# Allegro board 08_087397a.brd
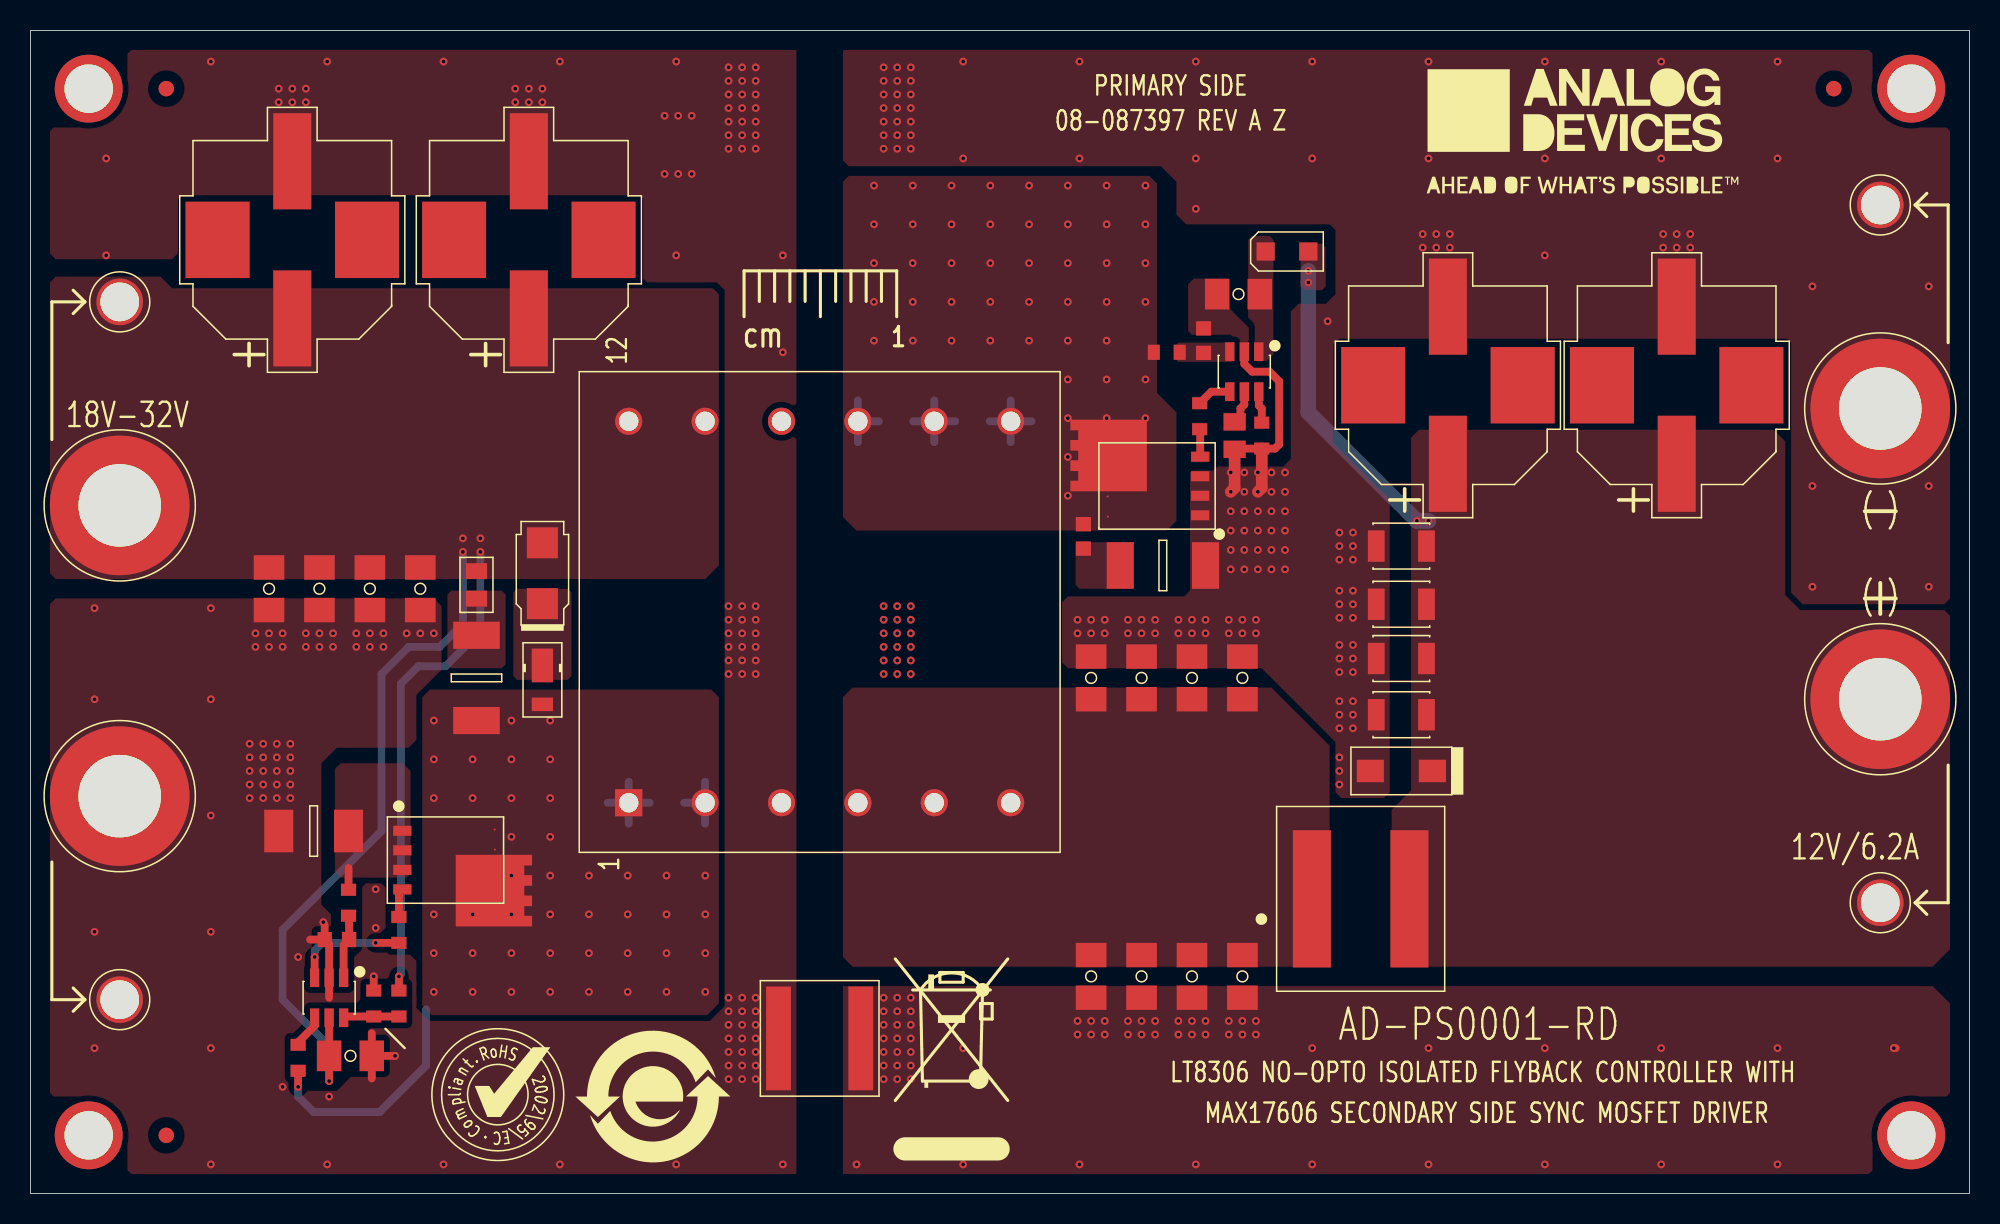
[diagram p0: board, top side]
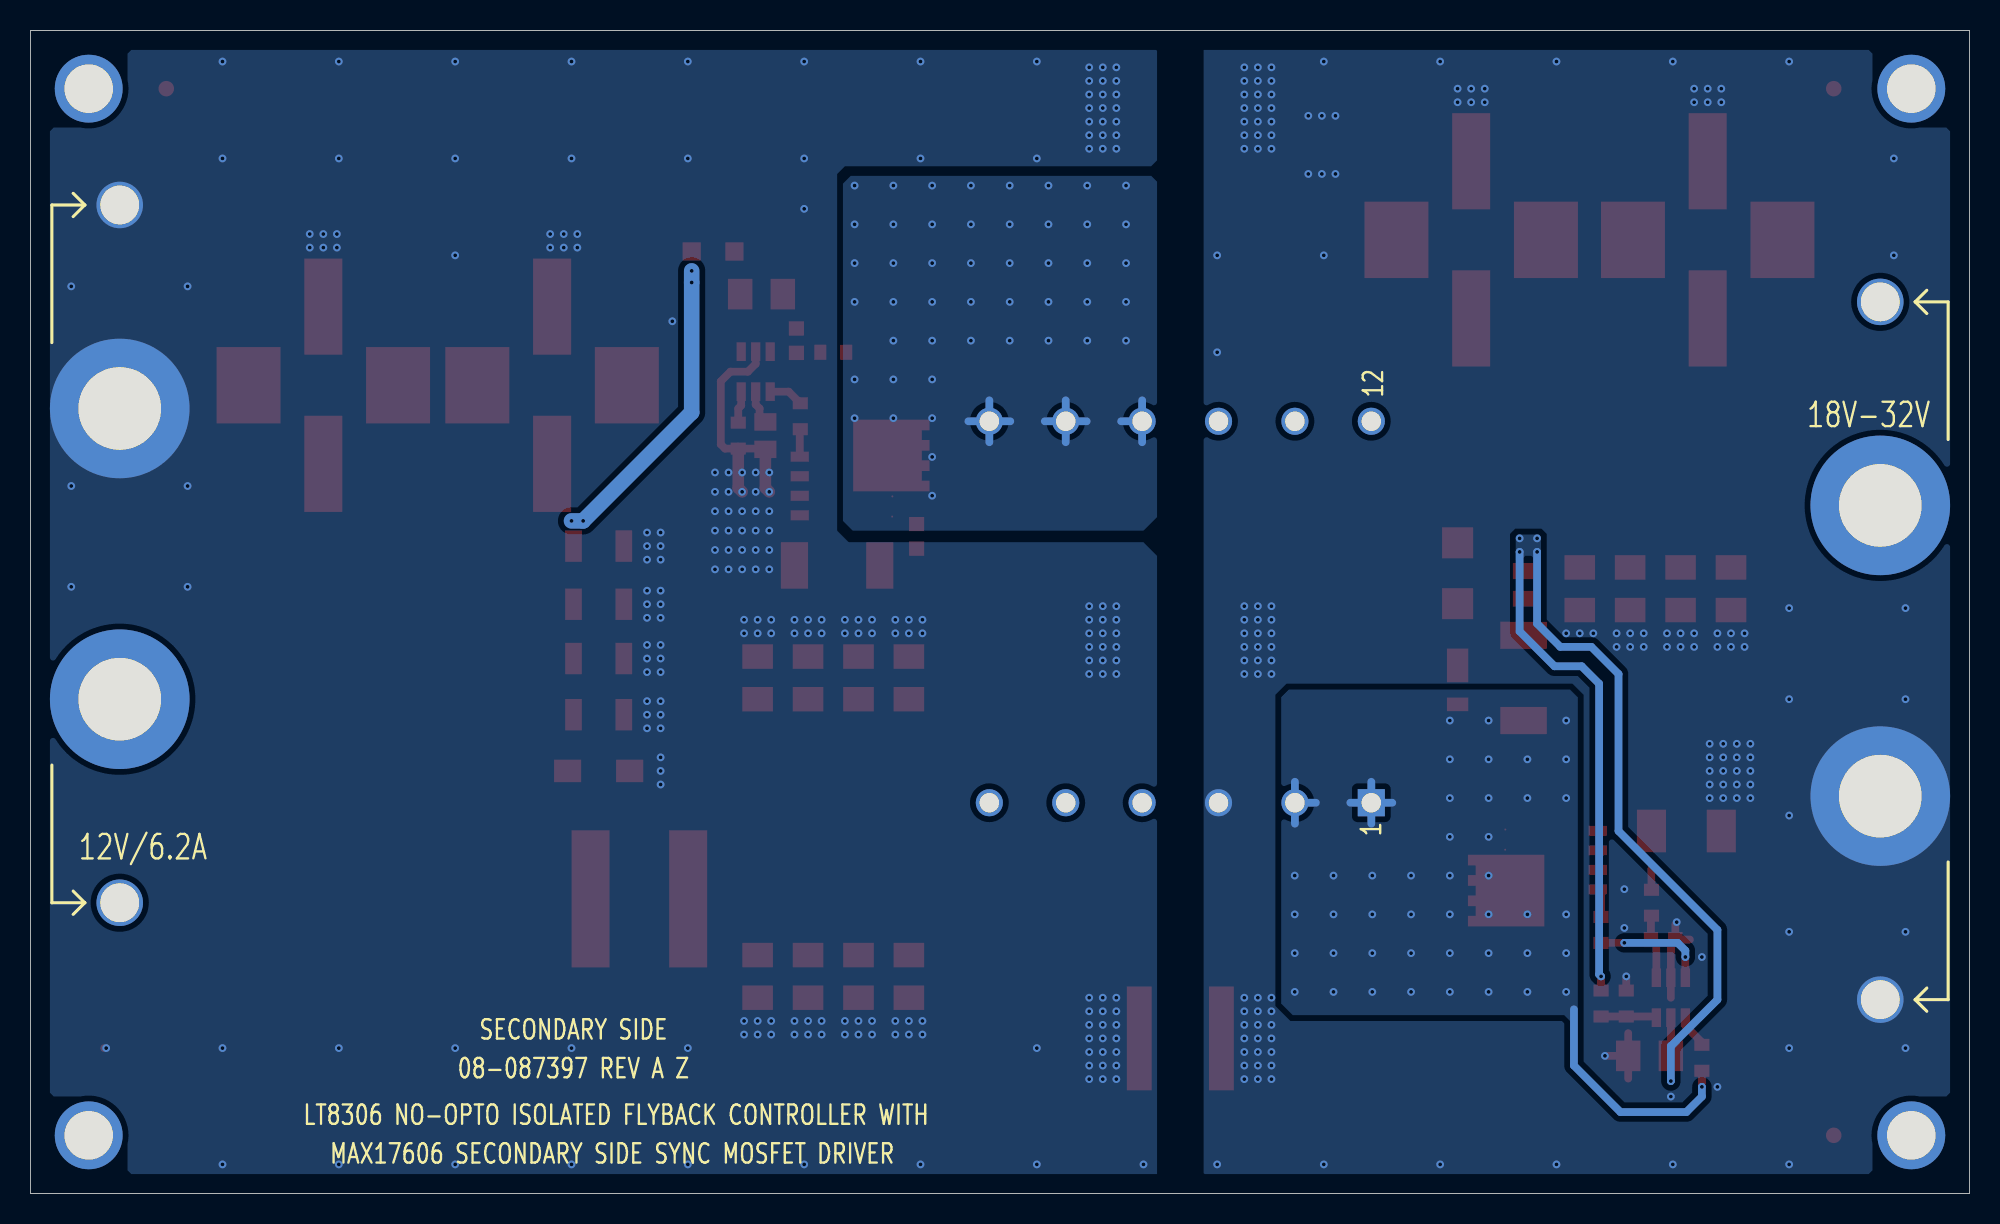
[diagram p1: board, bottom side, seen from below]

Outline 127 x 76.2 mm; copper layers: TOP, L2_GND, L3_GND, BOTTOM. Coordinates in mm from the lower left corner of the outline.
Outline path: 0,76.2 0,0 127,0 127,76.2 0,76.2

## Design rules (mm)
constraint set DEFAULT: min track width 0.203
net group UNNAMED_4_CAP_I100_N1: nets UNNAMED_4_CAP_I109_N1 UNNAMED_4_CAP_I109_N2
net group UNNAMED_4_RES_I50_N1: nets UNNAMED_4_ADMAX17606_I110_GATE UNNAMED_4_RES_I50_N1
net group VOUT: nets UNNAMED_4_CAP_I83_N2 VOUT
net group VIN: nets UNNAMED_4_ADLT8306_I22_EN UNNAMED_4_ADLT8306_I22_RFB UNNAMED_4_CAP_I31_N2 UNNAMED_4_DIOSCHOTTKY_I24_P VIN

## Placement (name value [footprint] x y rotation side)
C1  220UF  [CPLSMSQ492H650]  17.14 62.48 90 top
C2  220UF  [CPLSMSQ492H650]  32.64 62.48 90 top
C3  10uF  [C1206H71]  15.62 39.62 90 top
C4  10uF  [C1206H71]  18.92 39.62 90 top
C5  10uF  [C1206H71]  22.22 39.62 90 top
C6  10uF  [C1206H71]  25.53 39.62 90 top
C7  1uF  [C1206H71]  20.95 9.02 180 top
C8  1000pF  [C0603]  20.07 16.64 180 top
C9  680PF  [C0805H30]  29.21 39.88 270 top
C10  2200PF  [C2225H106]  51.69 10.16 0 top
C11  10uF  [C1206H71]  69.47 14.22 90 top
C12  10uF  [C1206H71]  72.77 14.22 90 top
C13  22uF  [C1210H106]  89.79 35.05 0 top
C14  10uF  [C1206H71]  76.07 14.22 90 top
C15  22uF  [C1210H106]  89.79 31.37 0 top
C16  10uF  [C1206H71]  79.38 14.22 90 top
C17  22uF  [C1210H106]  89.79 38.61 0 top
C18  22uF  [C1210H106]  89.79 42.42 0 top
C19  10uF  [C1206H71]  69.47 33.78 270 top
C20  1uF  [C1206H71]  79.12 58.93 0 top
C21  10uF  [C1206H71]  72.77 33.78 270 top
C22  220UF  [CPLSMSQ492H650]  92.84 52.96 90 top
C23  10uF  [C1206H71]  76.07 33.78 270 top
C24  220UF  [CPLSMSQ492H650]  107.82 52.96 90 top
C25  10uF  [C1206H71]  79.38 33.78 270 top
C27  1000pF  [C0603]  76.84 55.88 90 top
C30  1000pF  [C0603]  68.96 43.05 270 top
C56  2.2UF  [C0805H55]  78.87 49.66 90 top
D1  1SMA5943BT3G  [SMA]  33.53 40.64 90 top
D2  DFLS1150-7  [POWERDI123]  33.53 33.66 270 top
D3  CMZ5928B TR13 PBFREE  [DO214AC-2]  89.79 27.69 180 top
D4  CRS01(TE85L,Q,M)  [DIO-CRS]  82.3 61.72 0 top
GND  575-4  [CNBANANAD312LD203]  5.84 26.04 0 top
L1  4.7UH  [LSML413W457H358]  87.12 19.3 0 top
NOREF  -  [unnamed]  123.19 3.81 0 top
NOREF#2  -  [#2]  -109.98 -101.6 0 top
NOREF#3  -  [#2]  3.81 74.93 0 top
NOREF#4  -  [#2]  69.6 19.05 0 top
NOREF#5  -  [#2]  0 0 0 top
NOREF#6  -  [unnamed]  3.81 72.39 0 top
NOREF#7  -  [#2]  1.91 26.04 0 top
NOREF#8  -  [#2]  125.09 51.44 0 top
NOREF#9  -  [unnamed]  118.11 72.39 180 top
NOREF#10  -  [#2]  -28.75 329.56 0 top
NOREF#11  -  [#2]  -32.51 375.29 0 top
NOREF#12  -  [#2]  -9.27 209.93 0 top
NOREF#13  -  [#2]  0 76.2 270 top
NOREF#14  -  [#2]  306.6 -22.44 0 top
NOREF#15  -  [#2]  275.68 85.49 0 top
NOREF#16  -  [#2]  101.09 69.6 0 top
NOREF#17  -  [unnamed]  8.89 72.39 0 top
NOREF#18  -  [#2]  307.77 -32.6 0 top
NOREF#19  -  [#2]  416.59 -22.44 90 top
NOREF#20  -  [#2]  -109.98 -101.6 0 top
NOREF#21  -  [#2]  127 76.2 180 top
NOREF#22  -  [#2]  127 0 90 top
NOREF#23  -  [#2]  0 76.2 0 top
NOREF#24  -  [#2]  46.74 60.45 0 top
NOREF#25  -  [unnamed]  8.89 3.81 0 top
NOREF#26  -  [unnamed]  3.81 3.81 0 top
NOREF#27  -  [#2]  344.2 -24.02 0 top
NOREF#28  -  [#2]  3.81 58.42 0 top
NOREF#29  -  [#2]  401.98 74.7 0 top
NOREF#30  -  [#2]  30.61 6.48 0 top
NOREF#31  -  [#2]  125.73 32.38 0 top
NOREF#32  -  [#2]  95.63 5.84 270 top
NOREF#33  -  [#2]  40.77 6.35 0 top
NOREF#34  -  [#2]  416.59 -46.57 90 top
NOREF#35  -  [#2]  127 0 90 top
NOREF#36  -  [#2]  1.91 45.09 0 top
NOREF#37  -  [#2]  65.79 95.76 0 top
NOREF#38  -  [#2]  50.16 1.36 0 top
NOREF#39  -  [#2]  344.83 79.78 0 top
NOREF#40  -  [#2]  243.71 408.31 0 top
NOREF#41  -  [#2]  369.78 69.63 0 top
NOREF#42  -  [#2]  287.69 -28.47 0 top
NOREF#43  -  [#2]  237.62 255.27 0 top
NOREF#44  -  [#2]  371.27 79.79 0 top
NOREF#45  -  [unnamed]  123.19 72.39 0 top
NOREF#46  -  [#2]  -109.98 -101.6 0 top
NOREF#47  -  [#2]  275.65 58.84 0 top
NOREF#48  -  [#2]  -28.8 352.43 0 top
NOREF#49  -  [#2]  275.53 79.8 0 top
Q1  BSC110N15NS5ATMA1  [SON8]  27.18 21.84 270 top
Q2  BSC037N08NS5ATMA1  [SON8]  73.79 46.36 90 top
R1  402K  [R0603]  24.13 12.45 90 top
R2  33.2K  [R0603]  22.48 12.45 270 top
R3  124K  [R0603]  17.53 8.89 270 top
R4  10  [R2512]  29.21 33.78 90 top
R5  0  [R0603]  24.13 17.27 90 top
R6  10  [R0603]  20.83 19.05 90 top
R7  0.004  [R2010]  18.54 23.75 180 top
R8  10  [R2512]  74.17 41.15 180 top
R9  2.49K  [R0603]  74.42 55.12 180 top
R10  0  [R0603]  76.58 50.93 90 top
R11  100K  [R0603]  80.64 49.66 90 top
TP3  2501-2-00-80-00-00-07-0  [CNMILLMAX2501]  5.84 58.42 0 top
TP4  2501-2-00-80-00-00-07-0  [CNMILLMAX2501]  5.84 12.7 0 top
TP7  2501-2-00-80-00-00-07-0  [CNMILLMAX2501]  121.16 19.05 0 top
TP8  2501-2-00-80-00-00-07-0  [CNMILLMAX2501]  121.16 64.77 0 top
U1  LT8306RS6#TRMPBF  [TSOT23_6]  19.56 12.83 180 top
U2  MAX17606AZT+  [TSOT23_6]  79.5 53.85 180 top
VIN  575-4  [CNBANANAD312LD203]  5.84 45.09 0 top
VOUTN  575-4  [CNBANANAD312LD203]  121.16 51.44 0 top
VOUTP  575-4  [CNBANANAD312LD203]  121.16 32.38 0 top
X1  750371740  [TTHSQ1220H984]  39.18 25.6 90 top

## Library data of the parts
C1 C2 C22 C24 = CAPP: User Part Number: UPN; Tolerance: 20; alternate symbols: (CPLSMSQ492H650); tolerance: 20
C3-C7 C11 C12 C14 C16 C19-C21 C23 C25 = CAP: Tolerance: 10; User Part Number: UPN; alternate symbols: (C1206H71); tolerance: 10
C8 C27 C30 = CAP: User Part Number: UPN; Tolerance: 5; alternate symbols: (C0603); tolerance: 5
C9 = CAP: Tolerance: 10; User Part Number: UPN; alternate symbols: (C0805H30); tolerance: 10
C10 = CAP: User Part Number: UPN; Tolerance: 10; alternate symbols: (C2225H106); tolerance: 10
C13 C15 C17 C18 = CAP: Tolerance: 10; User Part Number: UPN; alternate symbols: (C1210H106); tolerance: 10
C56 = CAP: User Part Number: UPN; Tolerance: 10; alternate symbols: (C0805H55); tolerance: 10
D1 = DIOZNR: User Part Number: UPN; Tolerance: 5; alternate symbols: (SMA); tolerance: 5
D2 = DIOSCHOTTKY: User Part Number: UPN; Tolerance: N/A; alternate symbols: (POWERDI123); tolerance: N/A
D3 = DIOZNR: User Part Number: UPN; Tolerance: 5; alternate symbols: (DO214AC-2); tolerance: 5
D4 = DIO: Tolerance: N/A; User Part Number: UPN; alternate symbols: (DIO-CRS); tolerance: N/A
GND VIN VOUTN VOUTP = CNTP1P: Tolerance: N/A; User Part Number: UPN; alternate symbols: (CNBANANAD312LD203); tolerance: N/A
L1 = IND_V9: User Part Number: UPN; Tolerance: 20; alternate symbols: (LSML413W457H358); tolerance: 20
Q1 Q2 = TRANNMOSFET8P: Tolerance: N/A; User Part Number: UPN; alternate symbols: (SON8); tolerance: N/A
R1 R3 R6 R9 R11 = RES: User Part Number: UPN; Tolerance: 1; alternate symbols: (R0603); tolerance: 1
R2 = RES: User Part Number: UPN; Tolerance: 0.1; alternate symbols: (R0603); tolerance: 0.1
R4 R8 = RES: Tolerance: 1; User Part Number: UPN; alternate symbols: (R2512); tolerance: 1
R5 R10 = RES: User Part Number: UPN; Tolerance: JUMPER; alternate symbols: (R0603); tolerance: JUMPER
R7 = RES: Tolerance: 1; User Part Number: UPN; alternate symbols: (R2010); tolerance: 1
TP3 TP4 TP7 TP8 = CNTP1P: User Part Number: UPN; Tolerance: N/A; alternate symbols: (CNMILLMAX2501); tolerance: N/A
U1 = ADLT8306: User Part Number: UPN; Tolerance: N/A; alternate symbols: (TSOT23_6); tolerance: N/A
U2 = ADMAX17606: User Part Number: UPN; Tolerance: N/A; alternate symbols: (TSOT23_6); tolerance: N/A
X1 = XFMR12P_V18: Tolerance: N/A; alternate symbols: (TTHSQ1220H984); tolerance: N/A

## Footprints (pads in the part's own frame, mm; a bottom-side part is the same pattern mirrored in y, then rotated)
C0603
  rect 0.94x0.991 smd: 1(-0.8,0) 2(0.8,0)
C0805H30
  rect 1.041x1.397 smd: 1(-0.9,0) 2(0.9,0)
C0805H55
  rect 1.143x1.448 smd: 1(-0.9,0) 2(0.9,0)
C1206H71
  rect 1.6x2.007 smd: 1(-1.397,0) 2(1.397,0)
C1210H106
  rect 1.092x2.057 smd: 1(-1.646,0) 2(1.646,0)
C2225H106
  rect 1.626x6.807 smd: 1(-2.693,0) 2(2.693,0)
CNBANANAD312LD203
  round 9.144 hole 5.41: 1(0,0)
CNMILLMAX2501
  round 3.048 hole 2.54: 1(0,0)
CPLSMSQ492H650
  rect 5.004x4.191 smd: (0,4.896) (0,-4.896)
  rect 6.299x2.489 smd: N(5.15,0) P(-5.15,0)
DIO-CRS
  rect 1.194x1.194 smd: A(1.4,0) C(-1.4,0)
DO214AC-2
  rect 1.778x1.473 smd: A(2.032,0) C(-2.032,0)
LSML413W457H358
  rect 2.489x8.992 smd: 1(-3.195,0) 2(3.195,0)
POWERDI123
  rect 0.889x1.397 smd: A(1.606,0)
  rect 2.21x1.397 smd: C(-0.945,0)
R0603
  rect 0.787x0.991 smd: 1(-0.85,0) 2(0.85,0)
R2010
  rect 1.905x2.794 smd: 1(-2.286,0) 2(2.286,0)
R2512
  rect 1.778x3.048 smd: 1(-2.794,0) 2(2.794,0)
SMA
  rect 2.032x2.032 smd: A(1.994,0) C(-1.994,0)
SON8
  rect 0.66x1.194 smd: 1(-1.92,-2.828) 2(-0.64,-2.828) 3(0.64,-2.828) 4(1.92,-2.828)
  custom 1.175x1.175 smd: 5(2,3.171)
  round 0.127 smd: 6(0.678,3.211) 7(-0.68,3.236) 8(-2.002,3.223)
TSOT23_6
  rect 0.61x1.219 smd: 1(-0.95,-1.31) 2(0,-1.31) 3(0.95,-1.31) 4(0.95,1.31) 5(0,1.31) 6(-0.95,1.31)
TTHSQ1220H984
  rect 1.778x1.778 hole 1.27: 1(0,0)
  round 1.778 hole 1.27: 2(0,-5.004) 3(0,-10.008) 4(0,-15.011) 5(0,-20.015) 6(0,-25.019) 7(24.994,-25.019) 8(24.994,-20.015) 9(24.994,-15.011) 10(24.994,-10.008) 11(24.994,-5.004) 12(24.994,0)
unnamed
  round 4.445 hole 3.175 unplated: (0,0)

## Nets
GND_ISO: C10.2(N2) C11.1 C12.1 C13.1 C14.1 C15.1 C16.1 C17.1 C18.1 C19.1 C20.1 C21.1 C22.N(N2) C23.1 C24.N(N2) C25.1 C27.2(N2) C56.1 D3.A(P) Q2.1 Q2.2 Q2.3(S3) R8.1 R11.1 TP8.1(N1) U2.2 VOUTN.1(N1)
PGND: C1.N(N2) C2.N(N2) C3.1 C4.1 C5.1 C6.1 C7.1 C8.2(N2) C10.1 GND.1(N1) R2.1 R7.2(N2) TP4.1(N1) U1.2 X1.3
VIN: C1.P C2.P C3.2(N2) C4.2(N2) C5.2(N2) C6.2(N2) C7.2(N2) C9.1 D1.A(P) R1.2(N2) TP3.1(N1) U1.5(VIN) VIN.1(N1) X1.11 X1.12
UNNAMED_4_ADLT8306_I22_EN: R1.1 R2.2(N2) U1.6
UNNAMED_4_ADLT8306_I22_GATE: R5.1 U1.3
UNNAMED_4_ADLT8306_I22_RFB: R3.1 U1.4
UNNAMED_4_ADLT8306_I22_SENSE: C8.1 R6.1 U1.1
UNNAMED_4_ADMAX17606_I110_GATE: R10.2(N2) U2.4
UNNAMED_4_ADMAX17606_I110_TOFF: R11.2(N2) U2.6
UNNAMED_4_ADMAX17606_I110_VDRV: C56.2(N2) U2.5
UNNAMED_4_ADMAX17606_I110_VIN: C20.2(N2) D4.C U2.1(VIN)
UNNAMED_4_CAP_I31_N2: C9.2(N2) R4.2(N2)
UNNAMED_4_CAP_I83_N2: C11.2(N2) C12.2(N2) C14.2(N2) C16.2(N2) C19.2(N2) C21.2(N2) C23.2(N2) C25.2(N2) L1.1 X1.4 X1.5 X1.6
UNNAMED_4_CAP_I100_N1: C27.1 R9.1 U2.3
UNNAMED_4_CAP_I109_N1: C30.1 Q2.5 Q2.6 Q2.7 Q2.8 R9.2(N2) X1.7 X1.8 X1.9(SEC_3)
UNNAMED_4_CAP_I109_N2: C30.2(N2) R8.2(N2)
UNNAMED_4_DIOSCHOTTKY_I24_N: D1.C D2.C
UNNAMED_4_DIOSCHOTTKY_I24_P: D2.A(P) Q1.5 Q1.6 Q1.7 Q1.8 R3.2(N2) R4.1 X1.1 X1.2
UNNAMED_4_RES_I19_N1: Q1.1 Q1.2 Q1.3(S3) R6.2(N2) R7.1
UNNAMED_4_RES_I26_N2: Q1.4 R5.2(N2)
UNNAMED_4_RES_I50_N1: Q2.4 R10.1
VOUT: C13.2(N2) C15.2(N2) C17.2(N2) C18.2(N2) C22.P C24.P D3.C D4.A(P) L1.2(N2) TP7.1(N1) VOUTP.1(N1)

Pads without a net: X1 10

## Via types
v1: diameter 0.508, hole 0.254, TOP to BOTTOM, 473 vias

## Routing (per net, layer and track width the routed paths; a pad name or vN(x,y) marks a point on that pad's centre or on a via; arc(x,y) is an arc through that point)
GND_ISO: length 16.7
  TOP w0.508: U2.2 79.5,54.36 80.01,53.85 81.15,53.85 81.79,53.21 81.79,49.09 81.51,48.81 R11.1 78.92,48.81 C56.1 ; v1(122.05,9.53) 122.17,9.53
  TOP w0.762: C56.1 78.87,46.23 v1(78.61,45.97) ; v1(80.39,45.97) 80.64,46.23 R11.1
  vias: v1(54.1,1.91) v1(55.88,73.79) v1(55.88,72.9) v1(55.88,72.01) v1(55.88,71.12) v1(55.88,70.23) v1(55.88,69.34) v1(55.88,68.45) v1(55.88,38.48) v1(55.88,37.59) v1(55.88,36.7) v1(55.88,35.81) v1(55.88,34.92) v1(55.88,34.04) v1(55.88,12.83) v1(55.88,11.94) v1(55.88,11.05) v1(55.88,10.16) v1(55.88,9.27) v1(55.88,8.38) v1(55.88,7.49) v1(56.77,73.79) v1(56.77,72.9) v1(56.77,72.01) v1(56.77,71.12) v1(56.77,70.23) v1(56.77,69.34) v1(56.77,68.45) v1(56.77,38.48) v1(56.77,37.59) v1(56.77,36.7) v1(56.77,35.81) v1(56.77,34.92) v1(56.77,34.04) v1(56.77,12.83) v1(56.77,11.94) v1(56.77,11.05) v1(56.77,10.16) v1(56.77,9.27) v1(56.77,8.38) v1(56.77,7.49) v1(57.66,73.79) v1(57.66,72.9) v1(57.66,72.01) v1(57.66,71.12) v1(57.66,70.23) v1(57.66,69.34) v1(57.66,68.45) v1(57.66,38.48) v1(57.66,37.59) v1(57.66,36.7) v1(57.66,35.81) v1(57.66,34.92) v1(57.66,34.04) v1(57.66,12.83) v1(57.66,11.94) v1(57.66,11.05) v1(57.66,10.16) v1(57.66,9.27) v1(57.66,8.38) v1(57.66,7.49) v1(61.09,74.17) v1(61.09,67.82) v1(61.09,9.53) v1(61.09,1.91) v1(68.58,37.59) v1(68.58,36.7) v1(68.58,11.3) v1(68.58,10.41) v1(68.71,74.17) v1(68.71,67.82) v1(68.71,1.91) v1(69.47,37.59) v1(69.47,36.7) v1(69.47,11.3) v1(69.47,10.41) v1(70.36,37.59) v1(70.36,36.7) v1(70.36,11.3) v1(70.36,10.41) v1(71.88,37.59) v1(71.88,36.7) v1(71.88,11.3) v1(71.88,10.41) v1(72.77,37.59) v1(72.77,36.7) v1(72.77,11.3) v1(72.77,10.41) v1(73.66,37.59) v1(73.66,36.7) v1(73.66,11.3) v1(73.66,10.41) v1(75.18,37.59) v1(75.18,36.7) v1(75.18,11.3) v1(75.18,10.41) v1(76.07,37.59) v1(76.07,36.7) v1(76.07,11.3) v1(76.07,10.41) v1(76.33,74.17) v1(76.33,67.82) v1(76.33,64.52) v1(76.33,1.91) v1(76.96,37.59) v1(76.96,36.7) v1(76.96,11.3) v1(76.96,10.41) v1(78.49,37.59) v1(78.49,36.7) v1(78.49,11.3) v1(78.49,10.41) v1(78.61,47.24) v1(78.61,44.7) v1(78.61,43.43) v1(78.61,42.16) v1(78.61,40.89) v1(79.38,37.59) v1(79.38,36.7) v1(79.38,11.3) v1(79.38,10.41) v1(79.5,47.24) v1(79.5,45.97) v1(79.5,44.7) v1(79.5,43.43) v1(79.5,42.16) v1(79.5,40.89) v1(80.26,37.59) v1(80.26,36.7) v1(80.26,11.3) v1(80.26,10.41) v1(80.39,47.24) v1(80.39,44.7) v1(80.39,43.43) v1(80.39,42.16) v1(80.39,40.89) v1(81.28,47.24) v1(81.28,45.97) v1(81.28,44.7) v1(81.28,43.43) v1(81.28,42.16) v1(81.28,40.89) v1(82.17,47.24) v1(82.17,45.97) v1(82.17,44.7) v1(82.17,43.43) v1(82.17,42.16) v1(82.17,40.89) v1(83.95,74.17) v1(83.95,67.82) v1(83.95,9.53) v1(83.95,1.91) v1(84.96,57.15) v1(85.73,43.31) v1(85.73,42.42) v1(85.73,41.53) v1(85.73,39.5) v1(85.73,38.61) v1(85.73,37.72) v1(85.73,35.94) v1(85.73,35.05) v1(85.73,34.16) v1(85.73,32.26) v1(85.73,31.37) v1(85.73,30.48) v1(85.73,28.57) v1(85.73,27.69) v1(85.73,26.8) v1(86.62,43.31) v1(86.62,42.42) v1(86.62,41.53) v1(86.62,39.5) v1(86.62,38.61) v1(86.62,37.72) v1(86.62,35.94) v1(86.62,35.05) v1(86.62,34.16) v1(86.62,32.26) v1(86.62,31.37) v1(86.62,30.48) v1(91.19,62.87) v1(91.19,61.98) v1(91.57,74.17) v1(91.57,67.82) v1(91.57,9.53) v1(91.57,1.91) v1(92.08,62.87) v1(92.08,61.98) v1(92.96,62.87) v1(92.96,61.98) v1(99.19,74.17) v1(99.19,67.82) v1(99.19,61.47) v1(99.19,9.53) v1(99.19,1.91) v1(106.81,74.17) v1(106.81,67.82) v1(106.81,9.53) v1(106.81,1.91) v1(106.93,62.87) v1(106.93,61.98) v1(107.82,62.87) v1(107.82,61.98) v1(108.71,62.87) v1(108.71,61.98) v1(114.43,74.17) v1(114.43,67.82) v1(114.43,9.53) v1(114.43,1.91) v1(116.71,59.44) v1(116.71,46.36) v1(116.71,39.75) v1(124.33,59.44) v1(124.33,46.36) v1(124.33,39.75)
PGND: length 19.5
  TOP w0.508: R2.1 v1(22.48,14.22) ; C7.1 v1(23.88,9.02) ; C7.1 22.35,7.53 ; C7.1 22.35,10.5 ; C8.2 19.27,17.62 ; C8.2 18.31,16.64 ; C8.2 19.56,16.34 U1.2 19.56,12.83
  L2_GND w0.508: 47.81,25.6 X1.3 ; X1.3 49.19,24.23 ; X1.3 49.19,26.98
  L3_GND w0.508: 47.81,25.6 X1.3 ; X1.3 49.19,24.23 ; X1.3 49.19,26.98
  vias: v1(4.19,38.35) v1(4.19,32.38) v1(4.19,17.14) v1(4.19,9.53) v1(4.95,67.82) v1(4.95,61.47) v1(11.81,74.17) v1(11.81,38.35) v1(11.81,32.38) v1(11.81,24.76) v1(11.81,17.14) v1(11.81,9.53) v1(11.81,1.91) v1(14.35,29.46) v1(14.35,28.57) v1(14.35,27.69) v1(14.35,26.8) v1(14.35,25.91) v1(14.73,36.7) v1(14.73,35.81) v1(15.24,29.46) v1(15.24,28.57) v1(15.24,27.69) v1(15.24,26.8) v1(15.24,25.91) v1(15.62,36.7) v1(15.62,35.81) v1(16.13,29.46) v1(16.13,28.57) v1(16.13,27.69) v1(16.13,26.8) v1(16.13,25.91) v1(16.26,72.39) v1(16.26,71.5) v1(16.51,36.7) v1(16.51,35.81) v1(16.51,6.98) v1(17.02,29.46) v1(17.02,28.57) v1(17.02,27.69) v1(17.02,26.8) v1(17.02,25.91) v1(17.14,72.39) v1(17.14,71.5) v1(17.53,15.49) v1(18.03,72.39) v1(18.03,71.5) v1(18.03,36.7) v1(18.03,35.81) v1(18.92,36.7) v1(18.92,35.81) v1(19.18,17.78) v1(19.43,74.17) v1(19.43,1.91) v1(19.56,6.35) v1(19.81,36.7) v1(19.81,35.81) v1(21.34,36.7) v1(21.34,35.81) v1(22.22,36.7) v1(22.22,35.81) v1(22.61,19.94) v1(22.61,17.4) v1(23.11,36.7) v1(23.11,35.81) v1(24.64,36.7) v1(25.53,36.7) v1(26.42,36.7) v1(27.05,74.17) v1(27.05,1.91) v1(31.75,72.39) v1(31.75,71.5) v1(32.64,72.39) v1(32.64,71.5) v1(33.53,72.39) v1(33.53,71.5) v1(34.67,74.17) v1(34.67,1.91) v1(41.53,70.61) v1(41.53,66.8) v1(42.29,74.17) v1(42.29,61.47) v1(42.29,1.91) v1(42.42,70.61) v1(42.42,66.8) v1(43.31,70.61) v1(43.31,66.8) v1(45.72,73.79) v1(45.72,72.9) v1(45.72,72.01) v1(45.72,71.12) v1(45.72,70.23) v1(45.72,69.34) v1(45.72,68.45) v1(45.72,38.48) v1(45.72,37.59) v1(45.72,36.7) v1(45.72,35.81) v1(45.72,34.92) v1(45.72,34.04) v1(45.72,12.83) v1(45.72,11.94) v1(45.72,11.05) v1(45.72,10.16) v1(45.72,9.27) v1(45.72,8.38) v1(45.72,7.49) v1(46.61,73.79) v1(46.61,72.9) v1(46.61,72.01) v1(46.61,71.12) v1(46.61,70.23) v1(46.61,69.34) v1(46.61,68.45) v1(46.61,38.48) v1(46.61,37.59) v1(46.61,36.7) v1(46.61,35.81) v1(46.61,34.92) v1(46.61,34.04) v1(46.61,12.83) v1(46.61,11.94) v1(46.61,11.05) v1(46.61,10.16) v1(46.61,9.27) v1(46.61,8.38) v1(46.61,7.49) v1(47.5,73.79) v1(47.5,72.9) v1(47.5,72.01) v1(47.5,71.12) v1(47.5,70.23) v1(47.5,69.34) v1(47.5,68.45) v1(47.5,38.48) v1(47.5,37.59) v1(47.5,36.7) v1(47.5,35.81) v1(47.5,34.92) v1(47.5,34.04) v1(47.5,12.83) v1(47.5,11.94) v1(47.5,11.05) v1(47.5,10.16) v1(47.5,9.27) v1(47.5,8.38) v1(47.5,7.49) v1(49.28,61.47) v1(49.28,55.12) v1(49.28,1.91)
VIN: length 78.2
  TOP w0.508: U1.5 C7.2 v1(19.56,7.37) ; R1.2 v1(24.13,14.22)
  BOTTOM w0.508: v1(29.46,42.04) 29.46,36.83 27.18,34.54 25.4,34.54 24.26,33.4 24.26,14.35 v1(24.13,14.22) ; v1(28.32,42.04) 28.32,37.34 26.8,35.81 24.76,35.81 22.99,34.04 22.99,23.75 16.51,17.27 16.51,12.7 19.56,9.65 v1(19.56,7.37)
  vias: v1(28.32,42.93) v1(29.46,42.93)
UNNAMED_4_ADLT8306_I22_EN: length 3.7
  TOP w0.508: R1.1 R2.2 20.59,11.6 U1.6
UNNAMED_4_ADLT8306_I22_GATE: length 7.5
  TOP w0.508: U1.3 v1(18.61,15.49) ; R5.1 v1(22.61,16.42)
  BOTTOM w0.508: v1(22.61,16.42) 19.12,16.42 18.61,15.91 v1(18.61,15.49)
UNNAMED_4_ADLT8306_I22_RFB: length 2.2
  TOP w0.508: U1.4 18.61,10.99 17.53,9.91 R3.1
UNNAMED_4_ADLT8306_I22_SENSE: length 4.2
  TOP w0.508: R6.1 20.87,18.16 C8.1 20.51,16.28 U1.1
UNNAMED_4_ADMAX17606_I110_GATE: length 2.3
  TOP w0.508: R10.2 77.34,52.54 U2.4
UNNAMED_4_ADMAX17606_I110_TOFF: length 2.1
  TOP w0.508: R11.2 80.64,51.44 80.45,51.63 U2.6
UNNAMED_4_ADMAX17606_I110_VDRV: length 2.2
  TOP w0.508: C56.2 79.25,50.94 79.25,51.44 79.5,51.69 U2.5
UNNAMED_4_ADMAX17606_I110_VIN: length 0.1
  TOP w0.508: 80.45,58.86 C20.2
UNNAMED_4_CAP_I109_N1: length 15.1
  BOTTOM w0.508: 57.82,50.6 X1.8 ; X1.8 59.19,49.22 ; X1.8 59.19,51.97 ; X1.8 60.57,50.6 ; X1.7 65.57,50.6 ; X1.7 64.2,51.97 ; X1.7 62.83,50.6 ; X1.7 64.2,49.22 ; X1.9 54.19,51.97 ; X1.9 54.19,49.22 ; X1.9 55.56,50.6
  vias: v1(55.25,66.04) v1(55.25,63.5) v1(55.25,60.96) v1(55.25,58.42) v1(55.25,55.88) v1(57.79,66.04) v1(57.79,63.5) v1(57.79,60.96) v1(57.79,58.42) v1(57.79,55.88) v1(60.33,66.04) v1(60.33,63.5) v1(60.33,60.96) v1(60.33,58.42) v1(60.33,55.88) v1(62.87,66.04) v1(62.87,63.5) v1(62.87,60.96) v1(62.87,58.42) v1(62.87,55.88) v1(65.41,66.04) v1(65.41,63.5) v1(65.41,60.96) v1(65.41,58.42) v1(65.41,55.88) v1(67.95,66.04) v1(67.95,63.5) v1(67.95,60.96) v1(67.95,58.42) v1(67.95,55.88) v1(67.95,53.34) v1(67.95,50.8) v1(67.95,48.26) v1(67.95,45.72) v1(70.48,66.04) v1(70.48,63.5) v1(70.48,60.96) v1(70.48,58.42) v1(70.48,55.88) v1(70.48,53.34) v1(70.48,50.8) v1(73.03,66.04) v1(73.03,63.5) v1(73.03,60.96) v1(73.03,58.42) v1(73.03,53.34) v1(73.03,50.8)
UNNAMED_4_DIOSCHOTTKY_I24_P: length 25
  TOP w0.508: R3.2 v1(17.53,6.98)
  BOTTOM w0.508: X1.1 39.18,26.98 ; X1.1 39.18,24.23 ; X1.1 40.55,25.6 ; X1.1 37.81,25.6 ; v1(17.53,6.98) 17.53,6.35 18.54,5.33 22.86,5.33 25.91,8.38 25.91,12.07 ; 42.81,25.6 X1.2 ; X1.2 44.18,24.23 ; X1.2 44.18,26.98
  vias: v1(26.42,30.99) v1(26.42,28.45) v1(26.42,25.91) v1(26.42,18.29) v1(26.42,15.75) v1(26.42,13.21) v1(28.96,28.45) v1(28.96,25.91) v1(28.96,18.29) v1(28.96,15.75) v1(28.96,13.21) v1(31.5,30.99) v1(31.5,28.45) v1(31.5,25.91) v1(31.5,23.37) v1(31.5,20.83) v1(31.5,18.29) v1(31.5,15.75) v1(31.5,13.21) v1(34.04,30.99) v1(34.04,28.45) v1(34.04,25.91) v1(34.04,23.37) v1(34.04,20.83) v1(34.04,18.29) v1(34.04,15.75) v1(34.04,13.21) v1(36.58,20.83) v1(36.58,18.29) v1(36.58,15.75) v1(36.58,13.21) v1(39.12,20.83) v1(39.12,18.29) v1(39.12,15.75) v1(39.12,13.21) v1(41.66,20.83) v1(41.66,18.29) v1(41.66,15.75) v1(41.66,13.21) v1(44.2,20.83) v1(44.2,18.29) v1(44.2,15.75) v1(44.2,13.21)
UNNAMED_4_RES_I19_N1: length 1.4
  TOP w0.508: R6.2 20.83,21.34
UNNAMED_4_RES_I26_N2: length 1.9
  TOP w0.508: R5.2 24.13,19.7 Q1.4
UNNAMED_4_RES_I50_N1: length 1.8
  TOP w0.508: Q2.4 76.62,50.04 R10.1
VOUT: length 20.1
  BOTTOM w1.016: v1(91.57,44.07) v1(90.81,44.07) 83.7,51.18 v1(83.7,59.69) v1(83.7,60.45)

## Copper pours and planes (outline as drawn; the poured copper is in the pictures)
GND_ISO on TOP: 53.21,13.59 124.59,13.59 125.73,12.45 125.73,6.6 125.48,6.35 123.76,6.35 123.48,6.4 123.19,6.41 121.35,5.65 120.59,3.81 120.6,3.52 120.65,3.24 120.65,1.52 120.4,1.27 109.6,1.27 53.21,1.27
GND_ISO on TOP: 78.36,59.94 78.49,59.82 78.49,58.04 79.81,56.72 79.81,54.55 79.2,54.55 79.2,55.69 78.62,56.26 76.07,56.26 75.82,56.52 75.82,59.56 76.2,59.94
GND_ISO on TOP: 53.21,74.84 53.25,74.9 53.32,74.93 120.4,74.93 120.65,74.68 120.65,72.96 120.65,72.95 120.6,72.67 120.59,72.39 121.35,70.55 123.19,69.79 123.47,69.8 123.75,69.85 123.76,69.85 125.48,69.85 125.73,69.6 125.73,60.33 125.73,60.32 125.73,38.99 125.35,38.61 116.08,38.61 115.32,39.37 115.32,55.75 115.06,56.01 85.74,56.01 85.34,55.61 85.34,49.15 89.03,45.47 89.03,26.29 88.65,25.91 85.85,25.91 85.47,26.29 85.47,29.49 85.47,29.59 80.64,34.42 67.95,34.42 67.56,34.8 67.56,38.73 67.95,39.12 75.56,39.12 75.95,39.5 75.95,47.24 76.07,47.37 77.47,47.37 77.72,47.62 82.04,47.62 82.55,48.13 82.55,57.79 83.06,58.29 84.84,58.29 85.47,58.93 85.47,63.12 85.09,63.5 75.69,63.5 75.06,64.14 75.06,66.29 74.04,67.31 53.59,67.31 53.21,67.69
GND_ISO on BOTTOM: 53.21,74.83 53.25,74.9 53.32,74.93 120.4,74.93 120.65,74.68 120.65,72.96 120.65,72.95 120.6,72.67 120.59,72.39 121.35,70.55 123.19,69.79 123.47,69.8 123.75,69.85 123.76,69.85 125.48,69.85 125.73,69.6 125.73,6.6 125.48,6.35 123.76,6.35 123.75,6.35 123.47,6.4 123.19,6.41 121.35,5.65 120.59,3.81 120.6,3.53 120.65,3.25 120.65,3.24 120.65,1.52 120.4,1.27 53.21,1.27 53.21,24.36 53.32,24.53 53.52,24.53 53.84,24.38 54.19,24.33 55.46,25.6 54.19,26.87 53.84,26.82 53.52,26.68 53.32,26.68 53.21,26.85 53.21,41.78 54.1,42.67 73.41,42.67 74.17,43.43 74.17,66.8 73.66,67.31 53.59,67.31 53.21,67.69
GND_ISO on L2_GND, L3_GND: 53.21,74.83 53.25,74.9 53.32,74.93 120.4,74.93 120.65,74.68 120.65,72.96 120.65,72.95 120.6,72.67 120.59,72.39 121.35,70.55 123.19,69.79 123.47,69.8 123.75,69.85 123.76,69.85 125.48,69.85 125.73,69.6 125.73,6.6 125.48,6.35 123.76,6.35 123.75,6.35 123.47,6.4 123.19,6.41 121.35,5.65 120.59,3.81 120.6,3.53 120.65,3.25 120.65,3.24 120.65,1.52 120.4,1.27 53.21,1.27 53.21,24.36 53.32,24.53 53.52,24.53 53.84,24.38 54.19,24.33 55.46,25.6 54.19,26.87 53.84,26.82 53.52,26.68 53.32,26.68 53.21,26.85 53.21,49.35 53.32,49.52 53.52,49.52 53.84,49.38 54.19,49.33 55.46,50.6 54.19,51.87 53.84,51.82 53.52,51.67 53.32,51.67 53.21,51.84
PGND on TOP: outline of 156 points within 1.27,1.27 50.16,74.93
PGND on BOTTOM: 6.6,74.93 50.16,74.93 50.16,51.84 50.06,51.67 49.86,51.67 49.54,51.82 49.19,51.87 47.92,50.6 49.19,49.33 49.54,49.38 49.86,49.52 50.06,49.52 50.16,49.35 50.16,1.37 50.13,1.3 50.06,1.27 6.6,1.27 6.35,1.52 6.35,3.24 6.35,3.25 6.4,3.53 6.41,3.81 5.65,5.65 3.81,6.41 3.53,6.4 3.25,6.35 3.24,6.35 1.52,6.35 1.27,6.6 1.27,42.35 1.42,42.54 1.65,42.45 3.44,40.75 5.84,40.13 10.8,45.09 5.84,50.04 3.44,49.42 1.65,47.72 1.42,47.63 1.27,47.82 1.27,69.6 1.52,69.85 3.24,69.85 3.25,69.85 3.53,69.8 3.81,69.79 5.65,70.55 6.41,72.39 6.4,72.67 6.35,72.95 6.35,72.96 6.35,74.68
PGND on L2_GND, L3_GND: 6.6,74.93 50.16,74.93 50.16,51.84 50.06,51.67 49.86,51.67 49.54,51.82 49.19,51.87 47.92,50.6 49.19,49.33 49.54,49.38 49.86,49.52 50.06,49.52 50.16,49.35 50.16,26.85 50.06,26.68 49.86,26.68 49.54,26.82 49.19,26.87 47.92,25.6 49.19,24.33 49.54,24.38 49.86,24.53 50.06,24.53 50.16,24.36 50.16,1.37 50.13,1.3 50.06,1.27 6.6,1.27 6.35,1.52 6.35,3.24 6.35,3.25 6.4,3.53 6.41,3.81 5.65,5.65 3.81,6.41 3.53,6.4 3.25,6.35 3.24,6.35 1.52,6.35 1.27,6.6 1.27,42.35 1.42,42.54 1.65,42.45 3.44,40.75 5.84,40.13 10.8,45.09 5.84,50.04 3.44,49.42 1.65,47.72 1.42,47.63 1.27,47.82 1.27,69.6 1.52,69.85 3.24,69.85 3.25,69.85 3.53,69.8 3.81,69.79 5.65,70.55 6.41,72.39 6.4,72.67 6.35,72.95 6.35,72.96 6.35,74.68
VIN on TOP: 9.27,59.31 44.7,59.31 45.09,58.93 45.09,41.15 44.2,40.26 1.65,40.26 1.27,40.64 1.27,59.69 1.65,60.07 8.51,60.07
VIN on BOTTOM: 28.19,43.18 29.59,43.18 29.72,43.05 29.72,41.53 29.34,41.53 29.08,41.78 28.7,41.78 28.45,41.53 28.07,41.53 28.07,43.05
UNNAMED_4_ADMAX17606_I110_VIN on TOP: 80.15,57.01 80.15,54.55 80.96,54.55 81.41,54.99 81.41,62.48 81.15,62.74 80.01,62.74 79.76,62.48 79.76,57.4
UNNAMED_4_CAP_I31_N2 on TOP: 27.3,39.24 27.3,34.67 27.56,34.42 30.86,34.42 31.11,34.67 31.11,39.24 30.86,39.5 27.56,39.5
UNNAMED_4_CAP_I83_N2 on TOP: 53.85,33.15 53.21,32.51 53.21,15.49 53.85,14.86 84.45,14.86 85.09,15.49 85.09,29.34 81.28,33.15
UNNAMED_4_CAP_I100_N1 on TOP: 78.74,55.75 75.18,55.75 74.93,55.5 74.93,54.74 75.18,54.48 78.74,54.48
UNNAMED_4_CAP_I109_N1 on TOP: 73.79,52.45 75.06,51.18 75.06,44.07 74.42,43.43 54.1,43.43 53.21,44.32 53.21,66.29 53.59,66.67 73.28,66.67 73.79,66.17
UNNAMED_4_CAP_I109_N1 on BOTTOM: 53.21,44.32 54.1,43.43 73.15,43.43 73.79,44.07 73.79,66.17 73.28,66.67 53.59,66.67 53.21,66.29
UNNAMED_4_CAP_I109_N2 on TOP: 72.26,42.67 68.58,42.67 68.45,42.55 68.45,39.88 68.71,39.62 72.26,39.62
UNNAMED_4_DIOSCHOTTKY_I24_N on TOP: 31.62,33.91 31.88,33.66 35.18,33.66 35.43,33.91 35.43,39.37 35.18,39.62 31.88,39.62 31.62,39.37
UNNAMED_4_DIOSCHOTTKY_I24_P on TOP: 26.16,33.02 44.58,33.02 45.09,32.51 45.09,12.45 44.32,11.68 26.29,11.68 25.65,12.32 25.65,32.51
UNNAMED_4_DIOSCHOTTKY_I24_P on BOTTOM: 44.58,33.02 26.16,33.02 25.65,32.51 25.65,11.05 25.91,11.05 26.54,11.68 44.32,11.68 45.09,12.45 45.09,32.51
UNNAMED_4_RES_I19_N1 on TOP: 24.89,27.69 24.89,20.95 24.64,20.7 20.32,20.7 19.94,21.08 19.94,27.81 20.32,28.19 24.38,28.19
VOUT on TOP: 83.19,62.23 83.19,59.44 83.44,59.18 84.58,59.18 84.84,59.44 84.84,61.98 84.58,62.23
VOUT on TOP: 90.93,50.04 114.17,50.04 114.93,49.28 114.93,39.21 115.92,38.23 125.35,38.23 125.73,37.85 125.73,16 124.59,14.86 89.15,14.86 89.15,25.15 90.42,26.42 90.42,49.53

Small or netless copper shapes (teardrops, artwork), in the pictures only: 1 on TOP

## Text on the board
Ref Des/Silkscreen Bottom: LT8306 NO-OPTO ISOLATED FLYBACK CONTROLLER WITH | MAX17606 SECONDARY SIDE SYNC MOSFET DRIVER | 18V-32V | 12V/6.2A
User.Comments: 5.    C27 IS DNI(DO NOT INSTALL) PART. | 4.    INSTALL STANDOFF (25513 AND 29341) ON FOUR CORNERS OF THE BOARD.
Ref Des/Silkscreen Top: LT8306 NO-OPTO ISOLATED FLYBACK CONTROLLER WITH | MAX17606 SECONDARY SIDE SYNC MOSFET DRIVER | 18V-32V | 12V/6.2A | ( ) | AD-PS0001-RD
PAGE_OUTLINE: TEST PROCESS | FAB NOTES REVISION: 2ND NOVEMBER 2022 | N/A | 8.   IMPEDANCE REQUIREMENTS: IF NO STACKUP IS DEFINED, THE VENDOR IS ALLOWED TO ADJUST THE DIELECTRIC | 13.  PLATING SPECIFICATION: | 1.   DIMENSIONS ARE IN INCHES (EXCEPT WHERE NOTED). | ALL DOCUMENTS & SPECIFICATIONS REFERRED TO BELOW SHOULD BE THE LATEST REVISIONS. | 2.  BOARD MATERIAL:(USE CHECKED ITEMS) | 3.   ALL LAMINATES & BONDING MATERIALS SHOULD BE SELECTED FROM IPC-4101 OR IPC-4103,(TG>170 DEGC TD>300 DEGC) | 4.   REFER TO IPC-6010 SERIES, CLASS 2 FOR FABRICATION. | 5.   REFER TO LAMINATION DIAGRAM FOR OVERALL BOARD THICKNESS, TOLERANCE APPLIES AFTER ALL LAMINATION AND PLATING | 6.   BOW & TWIST NOT TO EXCEED 0.0075 INCHES (0.75%) PER LINEAR INCH AND SHOULD BE MEASURED PER IPC-TM-650, METHOD 2.4.22. | 7.   ACCEPTABILITY PER ADI SPECIFICATION TST00115. | 9.   FILLET OPTIONS TO ENHANCE RELIABILITY AT PAD JUNCTIONS WHERE SPACING PERMITS. | 10.  THIEVING: | 11.  LAYER TO LAYER REGISTRATION SHALL BE WITHIN 0.003 INCHES. | 12.  DRILL SIZES ARE FINISHED HOLE SIZES. ALL HOLES SHALL BE LOCATED WITHIN 0.005 INCHES DTP,UNLESS SPECIFIED. | 14.  SURFACE FINISH: | 15.  SOLDERMASK: | 16.  APPLY SILKSCREEN TO BOTH SIDES USING A NON-CONDUCTIVE, EPOXY BASED INK PER ARTWORK. | (X) WHITE | ( ) OTHER | PROCESSES. FINISHED THICKNESS MEASURED FROM TOP COPPER TO BOTTOM COPPER. | (X)  ISOLA 370HR OR S1000-2 OR IT180 OR EQUIVALENT | ( )  ISOLA-FR408HR OR EQUIVALENT | ( )  ISOLA IS410 | ( )  MEGTRON 6 | ( )  NELCO-4000-13 | ( )  ROGERS 4350B | ( ) ROGERS 3003 | ( ) ARLON 85N | ( ) EM370D | ( )  OTHER ________________________ | ( ) FILLETS ALLOWED | (X) FILLETS NOT ALLOWED | ( ) VENDOR MAY ADD THIEVING TO COMPENSATE FOR LOW COPPER DENSITY AREAS MAINTAINING A MINIMUM | ( ) VENDOR MAY NOT ADD THIEVING TO COMPENSATE FOR LOW COPPER DENSITY AREAS. | (X) LPI | ( ) OTHER_________ | COLOR | (X) GREEN | HINDER PROPER SOLDER WICKING. BARREL RELIEF ON SOLDERMASK ALLOWED IN UNFILLED VIA IN PAD HOLES. | (X) REFER TO LAMINATION DIAGRAM FOR FINISHED COPPER WEIGHT/THICKNESS REQUIRMENTS | (X) IMMERSION GOLD (ENIG) 1.58-3.94 MICRO INCHES OVER 118-236 MICRO INCHES MIN. OF ELECTROLESS NICKEL PER IPC-4552 | ( ) OSP (ORGANIC SOLDERABILITY PRESERVATIVE) | ( ) IMMERSION SILVER | ( ) SOFT WIRE BONDABLE GOLD 30-50 MICRO INCHES OF SOFT WIRE | ( ) EDGE CONNECTOR FINGERS ARE TO BE PLATED WITH 100 MICRO-INCHES(.0001") OF LOW STRESS | THICKNESS & TRACE WIDTHS TO MEET THE IMPEDANCE REQUIREMENT. IF SPECIFIED, THE VENDOR MUST | TRACE WIDTH & SPACING THAT IMPACT THE REQUIREMENTS MUST HAVE WRITTEN APPROVAL FROM ADI. | MINIMUM BARREL PLATING OF 0.001 INCHES. PLATED HOLES SHALL NOT BE ROUGH OR IRREGULAR SO AS TO | SOLDERMASK OVER BARE COPPER OR BARE GOLD (BOTH SIDES) TO MEET IPC-SM-840. | IF PRESENT,DO NOT MODIFY SOLDERMASK DEFINED PADS (MASK OPENINGS LESS THAN COPPER PAD) WITHOUT APPROVAL. | MEET THE REQUIREMENTS LISTED IN THE IMPEDANCE TABLE. ANY ADJUSTMENT MADE TO THE DEFINED STACKUP, | UL FLAMMABILITY RATING 94V-0. BOARD MATERIAL & CONSTRUCTION SHALL MEET THE REQUIREMENTS OF UL796/UL796F. | BONDABLE GOLD OVER 100-150 MICRO INCHES OF NICKEL | NICKEL UNDER 30 MICRO-INCHES (.0003') OF GOLD | 0.100 INCH CLEARANCE FROM ALL COPPER FEATURES, | THE STARTING COPPER WEIGHT/THICKNESS CAN VARY AS LONG AS THE FINISHED COPPER | WEIGHT/THICKNESS IS NOT LESS THAN THE SPECIFIED VALUE. | UNLESS OTHERWISE SPECIFIED | HOMOGENOUS MATERIALS IN THIS BOARD SHALL BE COMPLAINT WITH THE EU DIRECTIVE 2002/95/EC | WORKMANSHIP SHALL CONFORM TO IPC-A-600, CLASS 2. | 21.  INTENTIONAL SHORTS: | 17.  FINAL ELECTRICAL TEST TO BE PERFORMED USING PROVIDED IPC-D-356A NETLIST OR ODB++ FORMAT FILE. | 22.  PEMNUTS: | 23.  MANUFACTURER TO ETCH/STAMP WITH PERMANENT NON-CONDUCTIVE INK | ON SECONDARY SIDE UNLESS OTHERWISE SPECIFIED: | 18.  A TIME DOMAIN REFLECTOMETER REPORT (TDR) FOR EACH IMPEDANCE CONTROLLED LAYER & A CERTIFICATE | 19.  IF PRESENT, ALL BLIND/BURIED VIAS WITH AN ASPECT RATIO <1:1 TO BE PLATED SHUT WITH COPPER WHEN | 20.  FOR VIA FILL INFORMATION REFER TO DRILL CHART: | 26.  BOARDS TO BE SHIPPED SINGULATED AFTER FABRICATION PROCESS. | 24.  MINIMUM DESIGN LINE WIDTH IS .020 INCH. | 25.  MINIMUM DESIGN LINE SPACING IS .008 INCH. | IS ACCEPTABLE, ALL OTHER INSTANCES MUST BE REPORTED. | IF AN INTENTIONAL SHORT REPORT IS SUPPLIED AND DOES NOT MATCH THE FAB DATA THEN | THE PCB SHALL HAVE A VERIFICATION STAMP. | ( )  NON-CONDUCTIVE EPOXY FILL ALL 0.XXXX INCHES DRILLED VIAS | ( )  COPPER FILL ALL 0.XXXX INCHES DRILLED VIAS | ( ) PEMNUTS TO BE INSTALLED BY FABRICATOR | ( ) PEMNUTS NOT TO BE INSTALLED BY FABRICATOR | ( ) NOT APPLICABLE | USED AS VIA-IN-PAD OR AS A STACKED VIA. BLIND/BURIED VIAS WITH AN ASPECT RATIO >1:1 TO BE FILLED | A. UL CODE-FLAMMABILITY RATING FOR THOSE APPROVED MATERIALS(IF APPLICABLE) | B. DATE CODE | C. LOT NUMBER | D. MANUFACTURER LOGO | CAN'T BE PERFORMED BECAUSE THE TRACE LENGTH IS TOO SHORT ON THE OUTER LAYERS AT THE PIN ESCAPES | ADI APPROVAL IS REQUIRED. | OF COMPLIANCE SHALL BE PROVIDED BY VENDOR AT TIME OF SHIPMENT. INSTANCES WHERE TDR TESTING | WITH NON-CONDUCTIVE EPOXY. | SMOOTHEN EDGES AND FREE FROM BURRS AFTER DEPANELIZATION PROCESS. | LT8306 CUSTOMIZED EVKIT WITH | LT8309 FOR SECONDARY RECTIFICATION | NOTES: | TOOLING: | FINISH: | MATERIAL: | TESTING: | MISCELLANEOUS:
BODY_CENTER: LABEL PLACEMENT INFORMATION | HALF SIZE LABELS ARE | AVAILABLE IN THE LIBRARY | PLACE WHEELIE BIN LOGO | TO SUIT THE LAYOUT. | PLACE ROHS COMPLIANT LOGO | TO SUIT THE LAYOUT OR | DELETE IF NOT REQ'D. | PLACE CHINA ROHS COMPLIANT | LOGO TO SUIT THE LAYOUT OR | 1.THE BOARD SIZE CAN BE ADJUSTED TO SUIT THE APPLICATION. | 2.THE MOUNTING HOLES CAN BE MOVED/REMOVED TO SUIT THE APPLICATION. | 3.THE FIDUCIALS CAN BE MOVED TO SUIT THE APPLICATION. | 4.ADJUST THE DIMENSIONS TO SUIT THE APPLICATION. | 5.ADD THE CORRECT LAYER STACKUP ON FAB2 BASED ON THE NO OF LAYERS ON THE PCB. | 6.THE ROHS COMPLIANT AND WHEELIE BIN LOGO'S CAN BE MOVED TO THE DESIRED LOCATION. | HALF SIZE VERSIONS OF THE LABELS ARE AVAILABLE IN THE LIBRARY. | NOTES FOR TEMPLATE USAGE. | GENERIC D-SIZE TEMPLATE BR-067706A
DIMENSION: REF | DIA MAX
User.11: SEE ASSY NOTE4 | 4 PLACES | SEE DETAIL B | SEE DETAIL A
User.17: L2 GND | 08-      -06
User.18: L3 GND | 08-      -07
User.23: L2 GND | 08-      -07
User.24: L3 GND | 08-      -08
User.45: FIGURE | SIZE | 10.0 | 50.0 | 100.0 | 213.0 | 125.0 | DRILL CHART: TOP to BOTTOM | FINISHED HOLES IN MILS | PLATED | NON-PLATED | QTY | 473 | 12 | 4 | 497 | TOLERANCE/NOTES | TOTAL HOLES:
